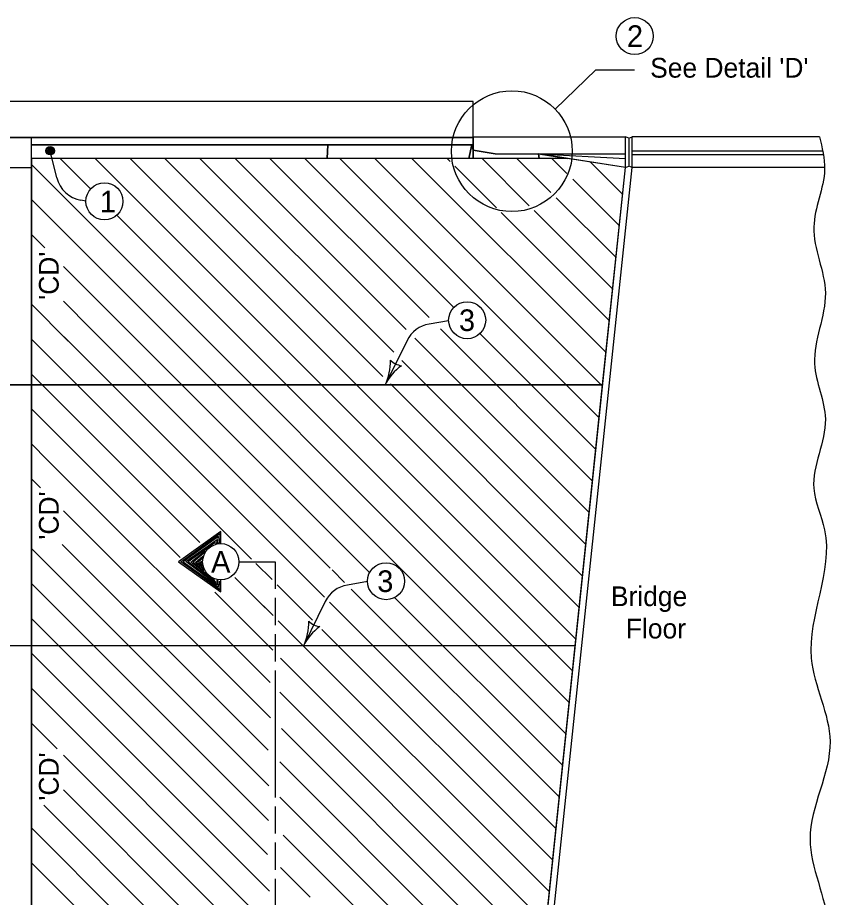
# Model space of a CAD drawing. Extents: x 10045 to 81668, y 6370 to 11018.
# Drawn here: x 11617 to 12310, y 6828 to 7576 of the extents above; entities that cross this region are included whole.
import ezdxf

# ---------------------------------------------------------------- set-up
doc = ezdxf.new("R2010")
doc.units = 0
for name, color, linetype in [('Alignment', 7, 'Continuous'), ('Default', 7, 'Continuous'), ('dsnStdLineWork', 7, 'Continuous')]:
    doc.layers.add(name, color=color, linetype=linetype)

msp = doc.modelspace()

# ---------------------------------------------------------------- linework, layer by layer
at = {"layer": 'Alignment'}
for p, q in [((12073.85, 7498.6), (12108.31, 7532.04)), ((12073.85, 7498.6), (12108.31, 7532.04)), ((12108.31, 7532.04), (12141.38, 7532.04)), ((12108.31, 7532.04), (12141.38, 7532.04)), ((11649.93, 7440.23), (11644.22, 7463.16)), ((11649.93, 7440.23), (11644.22, 7463.16)), ((11983.2, 7318.52), (11966.58, 7315.73)), ((11983.2, 7318.52), (11966.58, 7315.73)), ((11947.79, 7301.75), (11929.12, 7263.89)), ((11947.79, 7301.75), (11929.12, 7263.89)), ((12114.2, 7263.89), (11628.28, 7263.89)), ((11628.28, 7263.89), (11628.28, 7263.88)), ((11628.28, 7263.89), (11628.28, 6819.81)), ((12114.2, 7263.89), (11628.28, 7263.89)), ((11628.28, 7263.89), (11628.28, 7263.88)), ((11628.28, 7263.89), (11628.28, 6819.81)), ((12067.52, 6819.81), (12114.2, 7263.88)), ((12067.52, 6819.81), (12114.2, 7263.88)), ((11914.18, 7096.56), (11897.05, 7093.69)), ((11914.18, 7096.56), (11897.05, 7093.69)), ((11878.26, 7079.71), (11859.59, 7041.85)), ((11878.26, 7079.71), (11859.59, 7041.85))]:
    msp.add_line(p, q, dxfattribs=at)
for points in [[(11804.78, 7113.52), (11835.61, 7113.52), (11835.61, 7090.39)], [(11804.78, 7113.52), (11835.61, 7113.52), (11835.61, 7090.39)], [(11835.61, 7082.68), (11835.61, 7059.55)], [(11835.61, 7082.68), (11835.61, 7059.55)], [(11835.61, 7051.84), (11835.61, 7028.72)], [(11835.61, 7051.84), (11835.61, 7028.72)], [(11835.61, 7021), (11835.61, 6913.07)], [(11835.61, 7021), (11835.61, 6913.07)], [(11835.61, 6905.36), (11835.61, 6882.23)], [(11835.61, 6905.36), (11835.61, 6882.23)], [(11835.61, 6874.52), (11835.61, 6851.39)], [(11835.61, 6874.52), (11835.61, 6851.39)], [(11835.61, 6843.69), (11835.61, 6735.75)], [(11835.61, 6843.69), (11835.61, 6735.75)]]:
    msp.add_lwpolyline(points, dxfattribs=at)
msp.add_circle((12036.97, 7462.8), 51.4, dxfattribs=at)
msp.add_circle((12036.97, 7462.8), 51.4, dxfattribs=at)
for centre, start, end in [((11674.87, 7446.44), 193.98455, 260.0697), ((11674.87, 7446.44), 193.98455, 260.0697), ((11970.83, 7290.38), 99.53228, 153.75417), ((11970.83, 7290.38), 99.53228, 153.75417), ((11901.31, 7068.35), 99.53228, 153.75417), ((11901.31, 7068.35), 99.53228, 153.75417)]:
    msp.add_arc(centre, 25.7, start, end, dxfattribs=at)
at = {"layer": 'Default'}
msp.add_line((11628.31, 7474.36), (10703.15, 7474.36), dxfattribs=at)
msp.add_line((11628.31, 7474.36), (10703.15, 7474.36), dxfattribs=at)
at = {"layer": 'dsnStdLineWork'}
for p, q in [((12004.15, 7505.2), (11591.3, 7505.2)), ((12004.15, 7505.2), (11591.3, 7505.2)), ((12004.15, 7468.19), (12004.15, 7505.2)), ((12004.15, 7468.19), (12004.15, 7505.2)), ((11628.31, 7474.36), (11258.25, 7474.36)), ((11258.25, 7474.36), (11628.31, 7474.36)), ((11628.31, 7474.36), (11258.25, 7474.36)), ((11258.25, 7474.36), (11628.31, 7474.36)), ((12004.15, 7474.36), (11628.31, 7474.36)), ((11628.31, 7112.29), (11628.31, 7474.36)), ((11628.31, 7474.36), (12004.15, 7474.36)), ((11628.31, 7468.19), (11628.31, 7474.36)), ((12004.15, 7474.36), (11628.31, 7474.36)), ((11628.31, 7112.29), (11628.31, 7474.36)), ((11628.31, 7474.36), (12004.15, 7474.36)), ((11628.31, 7468.19), (11628.31, 7474.36)), ((12004.15, 7475.13), (12133.67, 7475.13)), ((12004.15, 7475.13), (12004.15, 7463.57)), ((12004.15, 7475.13), (12133.67, 7475.13)), ((12004.15, 7475.13), (12004.15, 7463.57)), ((12004.15, 7474.36), (12004.15, 7468.19)), ((12004.15, 7474.36), (12004.15, 7468.19)), ((12133.66, 7448.92), (12133.66, 7475.14)), ((12133.66, 7448.93), (12133.66, 7475.14)), ((12133.66, 7448.92), (12133.66, 7475.14)), ((12133.66, 7448.93), (12133.66, 7475.14)), ((12133.67, 7448.92), (12133.67, 7475.14)), ((12133.67, 7448.92), (12133.67, 7475.14)), ((12136.46, 7473.98), (12133.68, 7475.12)), ((12136.46, 7473.98), (12133.68, 7475.12)), ((12136.46, 7473.98), (12139.25, 7475.14)), ((12136.46, 7473.98), (12139.25, 7475.14)), ((12136.46, 7473.98), (12136.46, 7450.08)), ((12136.46, 7473.98), (12136.46, 7450.08)), ((12298.6, 7475.14), (12139.25, 7475.14)), ((12139.25, 7448.92), (12139.25, 7475.14)), ((12298.6, 7475.14), (12139.25, 7475.14)), ((12139.25, 7448.92), (12139.25, 7475.14)), ((12004.15, 7468.19), (11628.31, 7468.19)), ((12004.15, 7468.19), (11628.31, 7468.19)), ((11628.31, 7456.63), (11628.31, 7468.19)), ((11628.31, 7468.19), (11880.49, 7468.19)), ((12004.15, 7468.19), (11628.31, 7468.19)), ((12004.15, 7468.19), (11628.31, 7468.19)), ((11628.31, 7456.63), (11628.31, 7468.19)), ((11628.31, 7468.19), (11880.49, 7468.19)), ((11879.79, 7456.63), (11880.49, 7468.19)), ((11880.49, 7468.19), (11879.79, 7456.63)), ((11879.79, 7456.63), (11880.49, 7468.19)), ((11880.49, 7468.19), (11879.79, 7456.63)), ((11880.49, 7468.19), (12002.8, 7468.19)), ((11880.49, 7468.19), (12002.8, 7468.19)), ((12002.8, 7468.19), (12000.4, 7456.63)), ((12000.4, 7456.63), (12002.8, 7468.19)), ((12002.8, 7468.19), (12000.4, 7456.63)), ((12000.4, 7456.63), (12002.8, 7468.19)), ((12002.8, 7468.19), (12004.15, 7463.57)), ((12004.15, 7463.57), (12002.8, 7468.19)), ((12002.8, 7468.19), (12004.15, 7468.19)), ((12002.8, 7468.19), (12004.15, 7463.57)), ((12004.15, 7463.57), (12002.8, 7468.19)), ((12002.8, 7468.19), (12004.15, 7468.19)), ((12004.15, 7468.19), (12004.15, 7468.19)), ((12004.15, 7468.19), (12004.15, 7463.57)), ((12004.15, 7468.19), (12004.15, 7468.19)), ((12004.15, 7468.19), (12004.15, 7463.57)), ((12004.15, 7463.57), (12004.15, 7456.63)), ((12022.65, 7460.49), (12004.15, 7463.57)), ((12004.15, 7456.63), (12004.15, 7463.57)), ((12004.15, 7463.57), (12004.15, 7463.57)), ((12004.15, 7463.57), (12022.65, 7460.49)), ((12004.15, 7463.57), (12004.15, 7456.63)), ((12004.15, 7463.57), (12004.15, 7463.57)), ((12004.15, 7463.57), (12004.15, 7456.63)), ((12022.65, 7460.49), (12004.15, 7463.57)), ((12004.15, 7456.63), (12004.15, 7463.57)), ((12004.15, 7463.57), (12004.15, 7463.57)), ((12004.15, 7463.57), (12022.65, 7460.49)), ((12004.15, 7463.57), (12004.15, 7456.63)), ((12004.15, 7463.57), (12004.15, 7463.57)), ((12301.61, 7462.8), (12139.25, 7462.8)), ((12301.61, 7462.8), (12139.25, 7462.8)), ((12084.31, 7456.63), (11628.28, 7456.63)), ((11628.28, 7456.63), (11628.28, 7263.88)), ((12084.31, 7456.63), (11628.28, 7456.63)), ((11628.28, 7456.63), (11628.28, 7263.88)), ((12084.33, 7456.63), (11628.31, 7456.63)), ((11879.79, 7456.63), (11628.31, 7456.63)), ((12084.33, 7456.63), (11628.31, 7456.63)), ((11879.79, 7456.63), (11628.31, 7456.63)), ((11678.87, 7430.52), (11652.76, 7456.63)), ((11678.87, 7430.52), (11652.76, 7456.63)), ((12091.49, 7047.6), (11682.46, 7456.63)), ((12091.49, 7047.6), (11682.46, 7456.63)), ((12094.31, 7074.48), (11712.16, 7456.63)), ((12094.31, 7074.48), (11712.16, 7456.63)), ((11927.25, 7271.24), (11741.86, 7456.63)), ((11927.25, 7271.24), (11741.86, 7456.63)), ((11936.46, 7291.73), (11771.56, 7456.63)), ((11936.46, 7291.73), (11771.56, 7456.63)), ((11947.12, 7311), (11801.49, 7456.63)), ((11947.12, 7311), (11801.49, 7456.63)), ((11966.53, 7321.29), (11831.19, 7456.63)), ((11966.53, 7321.29), (11831.19, 7456.63)), ((11987.59, 7329.93), (11860.88, 7456.63)), ((11987.59, 7329.93), (11860.88, 7456.63)), ((12000.4, 7456.63), (11879.79, 7456.63)), ((12000.4, 7456.63), (11879.79, 7456.63)), ((12111.28, 7235.93), (11890.58, 7456.63)), ((12111.28, 7235.93), (11890.58, 7456.63)), ((12114.11, 7262.81), (11920.28, 7456.63)), ((12114.11, 7262.81), (11920.28, 7456.63)), ((12117.12, 7291.47), (11951.96, 7456.63)), ((12117.12, 7291.47), (11951.96, 7456.63)), ((11984.57, 7453.95), (11981.89, 7456.63)), ((11984.57, 7453.95), (11981.89, 7456.63)), ((12004.15, 7456.63), (12000.4, 7456.63)), ((12004.15, 7456.63), (12000.4, 7456.63)), ((12060.28, 7456.63), (12004.15, 7456.63)), ((12060.28, 7456.63), (12004.15, 7456.63)), ((12051.79, 7416.43), (12011.59, 7456.63)), ((12051.79, 7416.43), (12011.59, 7456.63)), ((12022.65, 7460.49), (12133.67, 7460.49)), ((12022.65, 7460.49), (12059.66, 7460.49)), ((12022.65, 7460.49), (12133.67, 7460.49)), ((12022.65, 7460.49), (12059.66, 7460.49)), ((12070.26, 7427.66), (12041.29, 7456.63)), ((12070.26, 7427.66), (12041.29, 7456.63)), ((12059.66, 7460.49), (12133.67, 7456.63)), ((12133.67, 7448.92), (12059.66, 7460.49)), ((12059.66, 7460.49), (12060.28, 7456.63)), ((12060.28, 7456.63), (12059.66, 7460.49)), ((12059.66, 7460.49), (12084.33, 7456.63)), ((12059.66, 7460.49), (12133.67, 7456.63)), ((12133.67, 7448.92), (12059.66, 7460.49)), ((12059.66, 7460.49), (12060.28, 7456.63)), ((12060.28, 7456.63), (12059.66, 7460.49)), ((12059.66, 7460.49), (12084.33, 7456.63)), ((12084.33, 7456.63), (12060.28, 7456.63)), ((12084.33, 7456.63), (12060.28, 7456.63)), ((12083.76, 7443.86), (12070.99, 7456.63)), ((12083.76, 7443.86), (12070.99, 7456.63)), ((12133.64, 7448.92), (12084.31, 7456.63)), ((12133.64, 7448.92), (12084.31, 7456.63)), ((12302.12, 7459.72), (12139.25, 7459.72)), ((12302.12, 7459.72), (12139.25, 7459.72)), ((11258.22, 7448.92), (11628.28, 7448.92)), ((11258.22, 7448.92), (11628.28, 7448.92)), ((11628.28, 7448.92), (11628.28, 7263.88)), ((11628.28, 7448.92), (11628.28, 7263.88)), ((12085.84, 6993.86), (11628.31, 7451.39)), ((12085.84, 6993.86), (11628.31, 7451.39)), ((12023.79, 7414.74), (11988.47, 7450.06)), ((12023.79, 7414.74), (11988.47, 7450.06)), ((12048.1, 6634.79), (12133.67, 7448.92)), ((12048.1, 6634.79), (12133.67, 7448.92)), ((12053.68, 6634.79), (12139.25, 7448.92)), ((12053.68, 6634.79), (12139.25, 7448.92)), ((12131.26, 7426.05), (12103.72, 7453.6)), ((12131.26, 7426.05), (12103.72, 7453.6)), ((12114.2, 7263.88), (12133.64, 7448.92)), ((12114.2, 7263.88), (12133.64, 7448.92)), ((12133.68, 7448.94), (12136.46, 7450.08)), ((12133.68, 7448.94), (12136.46, 7450.08)), ((12139.25, 7448.92), (12136.46, 7450.08)), ((12139.25, 7448.92), (12136.46, 7450.08)), ((12302.95, 7448.92), (12139.25, 7448.92)), ((12302.95, 7448.92), (12139.25, 7448.92)), ((12128.44, 7399.18), (12088.73, 7438.89)), ((12128.44, 7399.18), (12088.73, 7438.89)), ((12083.01, 6966.98), (11628.31, 7421.69)), ((12083.01, 6966.98), (11628.31, 7421.69)), ((11674.65, 7420.39), (11670.44, 7421.13)), ((11674.65, 7420.39), (11670.44, 7421.13)), ((12125.62, 7372.31), (12074.69, 7423.23)), ((12125.62, 7372.31), (12074.69, 7423.23)), ((12119.97, 7318.56), (12027.95, 7410.57)), ((12119.97, 7318.56), (12027.95, 7410.57)), ((12122.79, 7345.43), (12055.82, 7412.4)), ((12122.79, 7345.43), (12055.82, 7412.4)), ((12088.66, 7020.73), (11700.95, 7408.44)), ((12088.66, 7020.73), (11700.95, 7408.44)), ((11639.81, 7380.49), (11628.31, 7391.99)), ((11639.81, 7380.49), (11628.31, 7391.99)), ((11915.99, 7104.3), (11655.47, 7364.83)), ((11915.99, 7104.3), (11655.47, 7364.83)), ((11659.68, 7301.22), (11628.31, 7332.59)), ((11659.68, 7301.22), (11628.31, 7332.59)), ((11679.37, 7311.23), (11655.47, 7335.13)), ((11679.37, 7311.23), (11655.47, 7335.13)), ((11882.51, 7108.09), (11675.69, 7314.9)), ((11882.51, 7108.09), (11675.69, 7314.9)), ((12105.63, 7182.18), (11976.19, 7311.62)), ((12105.63, 7182.18), (11976.19, 7311.62)), ((12108.46, 7209.06), (12009.86, 7307.66)), ((12108.46, 7209.06), (12009.86, 7307.66)), ((11630, 7301.21), (11628.31, 7302.89)), ((11815.48, 7115.72), (11628.31, 7302.89)), ((11630, 7301.21), (11628.31, 7302.89)), ((11815.48, 7115.72), (11628.31, 7302.89)), ((11859.94, 7100.96), (11656.02, 7304.88)), ((11859.94, 7100.96), (11656.02, 7304.88)), ((12102.81, 7155.31), (11954.37, 7303.75)), ((12102.81, 7155.31), (11954.37, 7303.75)), ((12099.96, 7128.22), (11943.44, 7284.75)), ((12099.96, 7128.22), (11943.44, 7284.75)), ((11771.5, 7130.01), (11628.31, 7273.2)), ((11771.5, 7130.01), (11628.31, 7273.2)), ((10703.15, 7263.89), (12114.22, 7263.89)), ((10703.15, 7263.89), (12114.22, 7263.89)), ((11628.28, 7263.88), (11258.22, 7263.88)), ((11628.28, 7263.88), (11258.22, 7263.88)), ((11628.28, 7263.88), (11258.22, 7263.88)), ((11628.28, 7263.88), (11258.22, 7263.88)), ((11628.28, 6819.81), (11628.28, 7263.89)), ((11628.28, 6819.81), (11628.28, 7263.89)), ((11628.28, 7263.88), (12114.2, 7263.88)), ((11628.28, 7263.88), (12114.2, 7263.88)), ((11628.31, 6819.82), (11628.31, 7263.89)), ((11628.31, 6819.82), (11628.31, 7263.89)), ((12097.14, 7101.35), (11933.7, 7264.79)), ((12097.14, 7101.35), (11933.7, 7264.79)), ((11754.77, 7117.03), (11628.31, 7243.5)), ((11754.77, 7117.03), (11628.31, 7243.5)), ((11642.1, 7200), (11628.31, 7213.8)), ((11642.1, 7200), (11628.31, 7213.8)), ((11831.31, 7010.79), (11636.11, 7205.99)), ((11831.31, 7010.79), (11636.11, 7205.99)), ((11635.93, 7176.48), (11628.31, 7184.1)), ((11635.93, 7176.48), (11628.31, 7184.1)), ((11831.78, 6980.63), (11655.47, 7156.94)), ((11831.78, 6980.63), (11655.47, 7156.94)), ((11829.56, 6953.15), (11654.4, 7128.31)), ((11829.56, 6953.15), (11654.4, 7128.31)), ((11830.29, 6922.72), (11628.31, 7124.7)), ((11830.29, 6922.72), (11628.31, 7124.7)), ((11628.31, 6609.34), (11628.31, 7112.29)), ((11628.31, 6609.34), (11628.31, 7112.29)), ((11832.94, 7098.26), (11819.24, 7111.96)), ((11832.94, 7098.26), (11819.24, 7111.96)), ((11877.59, 7083.31), (11856.88, 7104.02)), ((11877.59, 7083.31), (11856.88, 7104.02)), ((11894.72, 7095.88), (11884.08, 7106.52)), ((11894.72, 7095.88), (11884.08, 7106.52)), ((11827.17, 7074.34), (11801.44, 7100.06)), ((11827.17, 7074.34), (11801.44, 7100.06)), ((11829.95, 6893.36), (11628.31, 7095.01)), ((11829.95, 6893.36), (11628.31, 7095.01)), ((11842.52, 7088.68), (11837.24, 7093.97)), ((11842.52, 7088.68), (11837.24, 7093.97)), ((11867.32, 7063.88), (11840.43, 7090.77)), ((11867.32, 7063.88), (11840.43, 7090.77)), ((12077.37, 6913.23), (11900.36, 7090.24)), ((12077.37, 6913.23), (11900.36, 7090.24)), ((11833.53, 7038.27), (11784.18, 7087.62)), ((11833.53, 7038.27), (11784.18, 7087.62)), ((12080.19, 6940.11), (11937.27, 7083.03)), ((12080.19, 6940.11), (11937.27, 7083.03)), ((11833.81, 7067.7), (11825.59, 7075.92)), ((11833.81, 7067.7), (11825.59, 7075.92)), ((12074.54, 6886.36), (11881.89, 7079.01)), ((12074.54, 6886.36), (11881.89, 7079.01)), ((11829.21, 6864.41), (11628.31, 7065.31)), ((11829.21, 6864.41), (11628.31, 7065.31)), ((12068.89, 6832.61), (11838.24, 7063.26)), ((12068.89, 6832.61), (11838.24, 7063.26)), ((12071.72, 6859.49), (11875.37, 7055.83)), ((12071.72, 6859.49), (11875.37, 7055.83)), ((11628.31, 7041.85), (10112.01, 7041.85)), ((11628.31, 7041.85), (10112.01, 7041.85)), ((12090.88, 7041.85), (11628.31, 7041.85)), ((12090.88, 7041.85), (11628.31, 7041.85)), ((11830.75, 6833.17), (11628.31, 7035.61)), ((11830.75, 6833.17), (11628.31, 7035.61)), ((12066.07, 6805.74), (11840.25, 7031.56)), ((12066.07, 6805.74), (11840.25, 7031.56)), ((11957.18, 6677.04), (11628.31, 7005.91)), ((11957.18, 6677.04), (11628.31, 7005.91)), ((12063.24, 6778.86), (11839.64, 7002.47)), ((12063.24, 6778.86), (11839.64, 7002.47)), ((11650.08, 6954.44), (11628.31, 6976.21)), ((11650.08, 6954.44), (11628.31, 6976.21)), ((12060.42, 6751.99), (11840.91, 6971.5)), ((12060.42, 6751.99), (11840.91, 6971.5)), ((11929.98, 6674.54), (11655.47, 6949.05)), ((11929.98, 6674.54), (11655.47, 6949.05)), ((12057.6, 6725.11), (11839.5, 6943.21)), ((12057.6, 6725.11), (11839.5, 6943.21)), ((11912.72, 6662.1), (11655.47, 6919.35)), ((11912.72, 6662.1), (11655.47, 6919.35)), ((11980.56, 6772.45), (11839.69, 6913.32)), ((11980.56, 6772.45), (11839.69, 6913.32)), ((11900.29, 6644.83), (11638.85, 6906.27)), ((11900.29, 6644.83), (11638.85, 6906.27)), ((11888.35, 6627.08), (11628.31, 6887.12)), ((11888.35, 6627.08), (11628.31, 6887.12)), ((11964.37, 6758.94), (11842.31, 6881)), ((11964.37, 6758.94), (11842.31, 6881)), ((11858.65, 6627.08), (11628.31, 6857.42)), ((11858.65, 6627.08), (11628.31, 6857.42)), ((11865.47, 6828.15), (11840.22, 6853.39)), ((11865.47, 6828.15), (11840.22, 6853.39))]:
    msp.add_line(p, q, dxfattribs=at)
msp.add_lwpolyline([(11628.28, 7456.63), (11628.31, 7456.63), (11628.31, 7474.36), (11258.25, 7474.36), (11258.25, 7448.92), (11628.28, 7448.92)], close=True, dxfattribs=at)
msp.add_lwpolyline([(11628.28, 7456.63), (11628.31, 7456.63), (11628.31, 7474.36), (11258.25, 7474.36), (11258.25, 7448.92), (11628.28, 7448.92)], close=True, dxfattribs=at)
for points in [[(11644.5, 7459.86), (11643.29, 7460.41), (11641.4, 7460.99), (11641.03, 7462.91), (11641.29, 7464.59), (11642.5, 7466.15), (11644.29, 7465.99), (11646.19, 7465.72), (11647.1, 7464.21), (11647.27, 7462.62), (11646.15, 7460.54), (11644.77, 7460.36), (11642.87, 7460.84), (11641.32, 7462.05), (11641.37, 7463.85), (11642.58, 7465.3), (11644.28, 7465.46), (11646.17, 7465.09), (11646.46, 7464.02), (11646.84, 7462.74), (11645.95, 7461.17), (11644.58, 7461.22), (11643, 7461.47), (11641.86, 7462.36), (11642.44, 7463.93), (11643.63, 7464.84), (11645.21, 7464.9), (11645.61, 7464.04), (11646.11, 7463.08), (11645.34, 7461.83), (11644.17, 7461.55), (11643.13, 7462.1), (11643.05, 7463.27), (11643.6, 7464.1), (11644.67, 7464.39), (11645.19, 7463.95), (11645.49, 7463.3), (11644.93, 7462.37), (11644.19, 7462.18), (11643.45, 7462.63), (11643.58, 7463.26), (11644.12, 7463.66), (11644.86, 7463.64), (11644.84, 7463.11), (11644.2, 7462.82)], [(11644.5, 7459.86), (11643.29, 7460.41), (11641.4, 7460.99), (11641.03, 7462.91), (11641.29, 7464.59), (11642.5, 7466.15), (11644.29, 7465.99), (11646.19, 7465.72), (11647.1, 7464.21), (11647.27, 7462.62), (11646.15, 7460.54), (11644.77, 7460.36), (11642.87, 7460.84), (11641.32, 7462.05), (11641.37, 7463.85), (11642.58, 7465.3), (11644.28, 7465.46), (11646.17, 7465.09), (11646.46, 7464.02), (11646.84, 7462.74), (11645.95, 7461.17), (11644.58, 7461.22), (11643, 7461.47), (11641.86, 7462.36), (11642.44, 7463.93), (11643.63, 7464.84), (11645.21, 7464.9), (11645.61, 7464.04), (11646.11, 7463.08), (11645.34, 7461.83), (11644.17, 7461.55), (11643.13, 7462.1), (11643.05, 7463.27), (11643.6, 7464.1), (11644.67, 7464.39), (11645.19, 7463.95), (11645.49, 7463.3), (11644.93, 7462.37), (11644.19, 7462.18), (11643.45, 7462.63), (11643.58, 7463.26), (11644.12, 7463.66), (11644.86, 7463.64), (11644.84, 7463.11), (11644.2, 7462.82)], [(11789.36, 7128.94), (11789.36, 7139.22), (11753.38, 7113.52), (11789.36, 7087.82), (11789.36, 7098.1)], [(11789.36, 7128.94), (11789.36, 7139.22), (11753.38, 7113.52), (11789.36, 7087.82), (11789.36, 7098.1)], [(11788.35, 7097.09), (11788.44, 7089.64), (11755.32, 7113.54), (11788.51, 7137.57), (11788.28, 7129.66), (11786.88, 7129.27), (11787.43, 7135.01), (11757.49, 7113.54), (11787.43, 7091.74), (11787.12, 7097.24), (11786.03, 7097.48), (11786.11, 7093.83), (11759.51, 7113.61), (11786.18, 7132.38), (11785.64, 7129.2), (11784.48, 7128.89), (11784.63, 7129.97), (11761.75, 7113.3), (11785.02, 7095.77), (11783.86, 7097.71), (11763.77, 7113.14), (11776.1, 7122.92), (11775.33, 7121.13), (11765.87, 7113.07), (11775.02, 7106.08), (11774.16, 7107.95), (11767.8, 7112.84), (11774.16, 7118.34), (11773.54, 7115.94), (11769.43, 7112.75), (11773.62, 7109.5), (11773.39, 7111.21), (11770.99, 7112.68), (11773.31, 7114.08), (11773.16, 7112.6), (11772.38, 7112.68)], [(11788.35, 7097.09), (11788.44, 7089.64), (11755.32, 7113.54), (11788.51, 7137.57), (11788.28, 7129.66), (11786.88, 7129.27), (11787.43, 7135.01), (11757.49, 7113.54), (11787.43, 7091.74), (11787.12, 7097.24), (11786.03, 7097.48), (11786.11, 7093.83), (11759.51, 7113.61), (11786.18, 7132.38), (11785.64, 7129.2), (11784.48, 7128.89), (11784.63, 7129.97), (11761.75, 7113.3), (11785.02, 7095.77), (11783.86, 7097.71), (11763.77, 7113.14), (11776.1, 7122.92), (11775.33, 7121.13), (11765.87, 7113.07), (11775.02, 7106.08), (11774.16, 7107.95), (11767.8, 7112.84), (11774.16, 7118.34), (11773.54, 7115.94), (11769.43, 7112.75), (11773.62, 7109.5), (11773.39, 7111.21), (11770.99, 7112.68), (11773.31, 7114.08), (11773.16, 7112.6), (11772.38, 7112.68)]]:
    msp.add_lwpolyline(points, dxfattribs=at)
for centre, radius in [((12141.48, 7560.7), 15.75), ((12141.48, 7560.7), 15.75), ((11644.22, 7463.16), 3.6), ((11644.22, 7463.16), 3.6), ((11690.4, 7420.13), 15.75), ((11690.4, 7420.13), 15.75), ((11998.94, 7319), 15.75), ((11998.94, 7319), 15.75), ((11789.36, 7113.52), 15.42), ((11789.36, 7113.52), 15.42), ((11929.93, 7096.96), 15.75), ((11929.93, 7096.96), 15.75)]:
    msp.add_circle(centre, radius, dxfattribs=at)
for centre, radius, start, end in [((11889.31, 7283.52), 44.39, 333.75446, 1.82694), ((11889.31, 7283.52), 44.39, 333.75446, 1.82694), ((11945.58, 7297.27), 17.14, 226.02111, 261.48781), ((11945.58, 7297.27), 17.14, 226.02111, 261.48781), ((11968.93, 7244.26), 44.39, 125.68197, 153.75446), ((11968.93, 7244.26), 44.39, 125.68197, 153.75446), ((11819.78, 7061.48), 44.39, 333.75446, 1.82694), ((11819.78, 7061.48), 44.39, 333.75446, 1.82694), ((11876.05, 7075.23), 17.14, 226.02111, 261.48781), ((11876.05, 7075.23), 17.14, 226.02111, 261.48781), ((11899.41, 7022.22), 44.39, 125.68197, 153.75446), ((11899.41, 7022.22), 44.39, 125.68197, 153.75446)]:
    msp.add_arc(centre, radius, start, end, dxfattribs=at)
msp.add_spline([(12298.56, 7475.12), (12302.98, 7447.4), (12293.82, 7398.34), (12303.63, 7342.1), (12294.47, 7281.93), (12303.63, 7234.84), (12293.82, 7175.97), (12302.98, 7140.66), (12291.63, 7031.41), (12307.6, 6960.54), (12290.64, 6877.7), (12305.61, 6803.84), (12293.63, 6723.98), (12304.61, 6655.11), (12298.39, 6608.62)], degree=3, dxfattribs=at)
msp.add_spline([(12298.56, 7475.12), (12302.98, 7447.4), (12293.82, 7398.34), (12303.63, 7342.1), (12294.47, 7281.93), (12303.63, 7234.84), (12293.82, 7175.97), (12302.98, 7140.66), (12291.63, 7031.41), (12307.6, 6960.54), (12290.64, 6877.7), (12305.61, 6803.84), (12293.63, 6723.98), (12304.61, 6655.11), (12298.39, 6608.62)], degree=3, dxfattribs=at)

# ---------------------------------------------------------------- texts
at = {"layer": 'Alignment'}
for s, height, p in [('2', 18.37, (12134.89, 7551.51)), ('2', 18.37, (12134.89, 7551.51)), ("See Detail 'D'", 16.8, (12154.6, 7525.36)), ("See Detail 'D'", 16.8, (12154.6, 7525.36)), ('1', 18.37, (11686.51, 7410.83)), ('1', 18.37, (11686.51, 7410.83)), ('3', 18.37, (11992, 7309.81)), ('3', 18.37, (11992, 7309.81)), ('A', 18.37, (11781.16, 7104.33)), ('A', 18.37, (11781.16, 7104.33)), ('3', 18.37, (11922.48, 7087.78)), ('3', 18.37, (11922.48, 7087.78)), ('Bridge', 16.8, (12121.24, 7075.74)), ('Bridge', 16.8, (12121.24, 7075.74)), ('Floor', 16.8, (12133.93, 7048.25)), ('Floor', 16.8, (12133.93, 7048.25))]:
    msp.add_text(s, height=height, dxfattribs=at).set_placement(p)
for p in [(11651.47, 7336.32), (11651.47, 7336.32), (11651.47, 7132.31), (11651.47, 7132.31), (11651.47, 6910.27), (11651.47, 6910.27)]:
    msp.add_text("'CD'", height=16.8, rotation=90, dxfattribs=at).set_placement(p)

doc.saveas('drawing.dxf')
